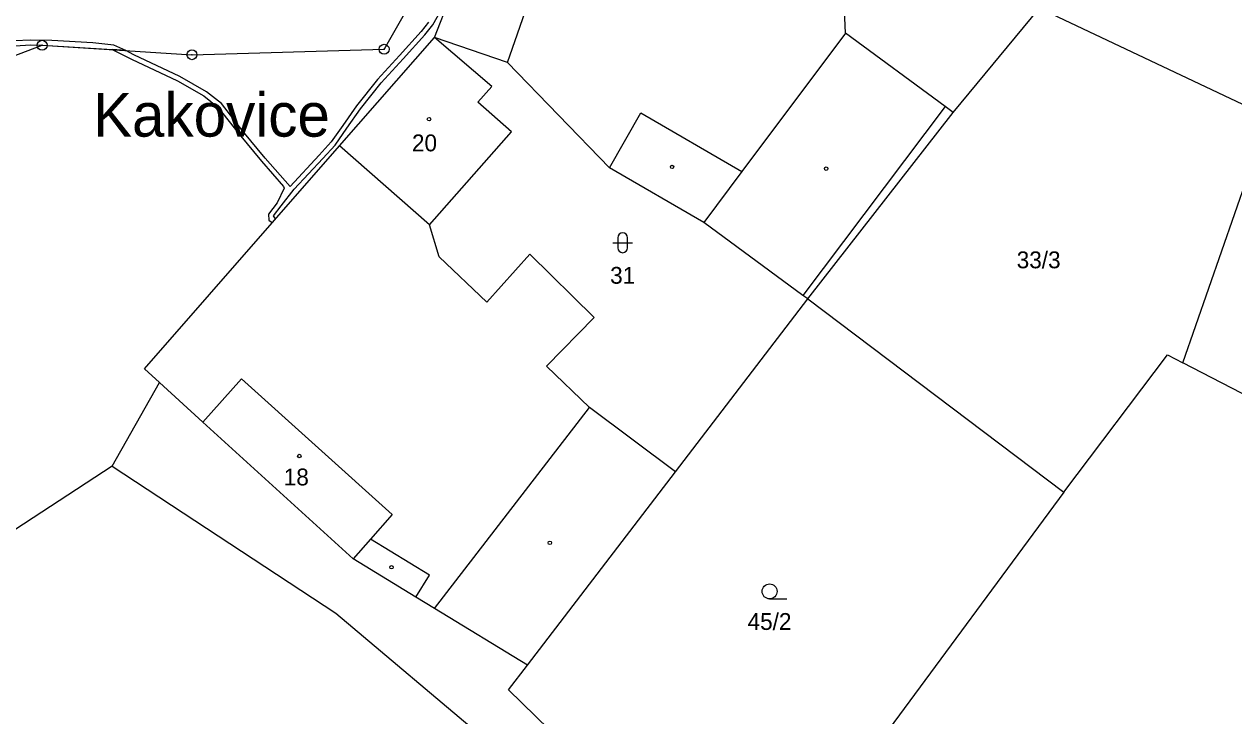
# Model space of a CAD drawing. Extents: x -791548 to -789311, y -1142631 to -1140855.
# Drawn here: x -790327.9 to -790206, y -1142288.4 to -1142218.6 of the extents above; entities that cross this region are included whole.
import ezdxf
from ezdxf.enums import TextEntityAlignment as Align

# ---------------------------------------------------------------- set-up
doc = ezdxf.new("R2010")
doc.units = 0
doc.header["$LTSCALE"] = 0.68
for name, color, linetype, lineweight in [('1', 7, 'Continuous', 25), ('13', 7, 'Continuous', 13), ('3', 7, 'Continuous', 25), ('4', 7, 'Continuous', 13), ('5', 7, 'Continuous', 25), ('7', 7, 'Continuous', 13), ('8', 7, 'Continuous', 25)]:
    doc.layers.add(name, color=color, linetype=linetype, lineweight=lineweight)
doc.layers.add('2', color=7, linetype='Continuous')

msp = doc.modelspace()

# ---------------------------------------------------------------- linework, layer by layer
at = {"layer": '1'}
for p, q in [((-790280.17, -1142200.89), (-790291.64, -1142221.17)), ((-790286.57, -1142220), (-790279.72, -1142202.49)), ((-790245.13, -1142219.55), (-790245.28, -1142216.42)), ((-790234.29, -1142227.54), (-790225.57, -1142217.02)), ((-790225.57, -1142217.02), (-790202.5, -1142227.96)), ((-790296.14, -1142230.9), (-790286.57, -1142220)), ((-790279.2, -1142222.5), (-790286.57, -1142220)), ((-790280.79, -1142224.94), (-790286.57, -1142220)), ((-790235.09, -1142226.94), (-790245.13, -1142219.55)), ((-790352.29, -1142230.61), (-790326.11, -1142220.77)), ((-790326.11, -1142220.77), (-790311.01, -1142221.72)), ((-790311.01, -1142221.72), (-790291.64, -1142221.17)), ((-790268.92, -1142233.12), (-790279.2, -1142222.5)), ((-790282.18, -1142226.52), (-790280.79, -1142224.94)), ((-790278.8, -1142229.49), (-790282.18, -1142226.52)), ((-790234.29, -1142227.54), (-790235.09, -1142226.94)), ((-790248.93, -1142246.33), (-790234.29, -1142227.54)), ((-790211.14, -1142252.78), (-790202.5, -1142227.96)), ((-790287.05, -1142238.88), (-790278.8, -1142229.49)), ((-790315.8, -1142253.39), (-790296.14, -1142230.9)), ((-790287.05, -1142238.88), (-790296.14, -1142230.9)), ((-790259.42, -1142238.65), (-790268.92, -1142233.12)), ((-790286.09, -1142242.1), (-790287.05, -1142238.88)), ((-790249.42, -1142245.98), (-790259.42, -1142238.65)), ((-790276.95, -1142241.83), (-790281.3, -1142246.66)), ((-790270.48, -1142248.23), (-790276.95, -1142241.83)), ((-790281.3, -1142246.66), (-790286.09, -1142242.1)), ((-790262.25, -1142263.78), (-790248.93, -1142246.33)), ((-790248.93, -1142246.33), (-790249.42, -1142245.98)), ((-790248.93, -1142246.33), (-790223.12, -1142265.83)), ((-790275.27, -1142253.13), (-790270.48, -1142248.23)), ((-790223.12, -1142265.83), (-790212.68, -1142251.98)), ((-790212.68, -1142251.98), (-790211.14, -1142252.78)), ((-790185.55, -1142266.07), (-790211.14, -1142252.78)), ((-790314.27, -1142254.78), (-790315.8, -1142253.39)), ((-790270.93, -1142257.29), (-790275.27, -1142253.13)), ((-790319.06, -1142263.2), (-790314.27, -1142254.78)), ((-790309.9, -1142258.76), (-790314.27, -1142254.78)), ((-790262.25, -1142263.78), (-790270.93, -1142257.29)), ((-790294.75, -1142272.55), (-790309.9, -1142258.76)), ((-790319.06, -1142263.2), (-790347.8, -1142282.01)), ((-790319.06, -1142263.2), (-790296.49, -1142278.02)), ((-790277.19, -1142283.25), (-790262.25, -1142263.78)), ((-790223.12, -1142265.83), (-790255.11, -1142309.11)), ((-790288.43, -1142276.4), (-790294.75, -1142272.55)), ((-790286.55, -1142277.55), (-790288.43, -1142276.4)), ((-790296.49, -1142278.02), (-790281.3, -1142290.85)), ((-790277.19, -1142283.25), (-790286.55, -1142277.55)), ((-790279.1, -1142285.75), (-790277.19, -1142283.25)), ((-790255.11, -1142309.11), (-790279.1, -1142285.75))]:
    msp.add_line(p, q, dxfattribs=at)
at = {"layer": '13'}
msp.add_lwpolyline([(-790332.65, -1142214.52), (-790333.14, -1142214.68), (-790332.28, -1142221), (-790331.71, -1142221.45), (-790328.85, -1142220.82), (-790327.24, -1142220.74), (-790326.11, -1142220.77), (-790319.06, -1142221.21), (-790317.66, -1142221.3), (-790318.89, -1142220.75), (-790321.01, -1142220.53), (-790325.13, -1142220.29), (-790327.24, -1142220.24), (-790328.91, -1142220.32), (-790331.59, -1142220.91), (-790331.82, -1142220.74)], close=True, dxfattribs=at)
msp.add_lwpolyline([(-790287.15, -1142218.44), (-790287.91, -1142219.39), (-790290.09, -1142221.81), (-790292.32, -1142224.23), (-790294.43, -1142226.89), (-790295.81, -1142228.85), (-790296.97, -1142230.51), (-790298.17, -1142231.85), (-790301.12, -1142235), (-790303.62, -1142232.14), (-790305.88, -1142229.42), (-790308.04, -1142226.64), (-790309.54, -1142225.45), (-790312.24, -1142223.91), (-790316.88, -1142221.74), (-790317.66, -1142221.3), (-790319.06, -1142221.21), (-790317.1, -1142222.18), (-790312.48, -1142224.35), (-790309.82, -1142225.87), (-790308.4, -1142227), (-790306.26, -1142229.74), (-790304, -1142232.46), (-790301.79, -1142234.99), (-790301.71, -1142235.18), (-790302.42, -1142236.66), (-790303.28, -1142237.81), (-790303.25, -1142238.39), (-790302.91, -1142238.64), (-790302.58, -1142238.27), (-790302.78, -1142237.97), (-790302.01, -1142236.94), (-790300.71, -1142235.29), (-790297.81, -1142232.19), (-790296.57, -1142230.83), (-790295.41, -1142229.13), (-790294.03, -1142227.19), (-790291.94, -1142224.55), (-790289.73, -1142222.15), (-790287.53, -1142219.71), (-790286.73, -1142218.72), (-790285.67, -1142216.85)], dxfattribs=at)
at = {"layer": '3'}
for p, q in [((-790268.591, -1142240.681), (-790266.589, -1142240.681)), ((-790268.091, -1142240.181), (-790268.091, -1142241.182)), ((-790267.089, -1142241.182), (-790267.089, -1142240.181)), ((-790252.783, -1142276.58), (-790251.033, -1142276.58))]:
    msp.add_line(p, q, dxfattribs=at)
msp.add_circle((-790252.7829, -1142275.8298), 0.75, dxfattribs=at)
for centre, start, end in [((-790267.59, -1142240.1809), 0, 180), ((-790267.59, -1142241.1809), 180, 359.98789)]:
    msp.add_arc(centre, 0.5, start, end, dxfattribs=at)
at = {"layer": '4'}
for p, q in [((-790279.2, -1142222.5), (-790273, -1142204.78)), ((-790245.13, -1142219.55), (-790255.58, -1142233.51)), ((-790235.09, -1142226.94), (-790249.42, -1142245.98)), ((-790268.92, -1142233.12), (-790265.77, -1142227.57)), ((-790265.77, -1142227.57), (-790255.58, -1142233.51)), ((-790255.58, -1142233.51), (-790259.42, -1142238.65)), ((-790309.9, -1142258.76), (-790306.01, -1142254.41)), ((-790306.01, -1142254.41), (-790290.82, -1142268.06)), ((-790286.55, -1142277.55), (-790270.93, -1142257.29)), ((-790290.82, -1142268.06), (-790293, -1142270.55)), ((-790293, -1142270.55), (-790294.75, -1142272.55)), ((-790287.08, -1142274.18), (-790293, -1142270.55)), ((-790288.43, -1142276.4), (-790287.08, -1142274.18))]:
    msp.add_line(p, q, dxfattribs=at)
at = {"layer": '5'}
for centre in [(-790287.1088, -1142228.2133), (-790262.6088, -1142233.0333), (-790247.0788, -1142233.2033), (-790300.1888, -1142262.1833), (-790274.9288, -1142270.9333), (-790290.8988, -1142273.3933)]:
    msp.add_circle(centre, 0.175, dxfattribs=at)
at = {"layer": '8'}
for centre, radius in [((-790326.1099, -1142220.77), 0.5), ((-790326.1099, -1142220.77), 0.0303), ((-790311.0099, -1142221.72), 0.5), ((-790291.6399, -1142221.17), 0.5), ((-790291.6399, -1142221.17), 0.0303), ((-790311.0099, -1142221.72), 0.0303)]:
    msp.add_circle(centre, radius, dxfattribs=at)

# ---------------------------------------------------------------- texts
at = {"layer": '2'}
for s, p in [('20', (-790287.569, -1142231.462)), ('33/3', (-790225.659, -1142243.252)), ('31', (-790267.589, -1142244.812)), ('18', (-790300.489, -1142265.142)), ('45/2', (-790252.789, -1142279.712))]:
    msp.add_text(s, height=1.7, dxfattribs=at).set_placement(p, align=Align.CENTER)
at = {"layer": '7'}
msp.add_text('Kakovice', height=4.4, dxfattribs=at).set_placement((-790309.039, -1142229.98), align=Align.CENTER)

doc.saveas('drawing.dxf')
